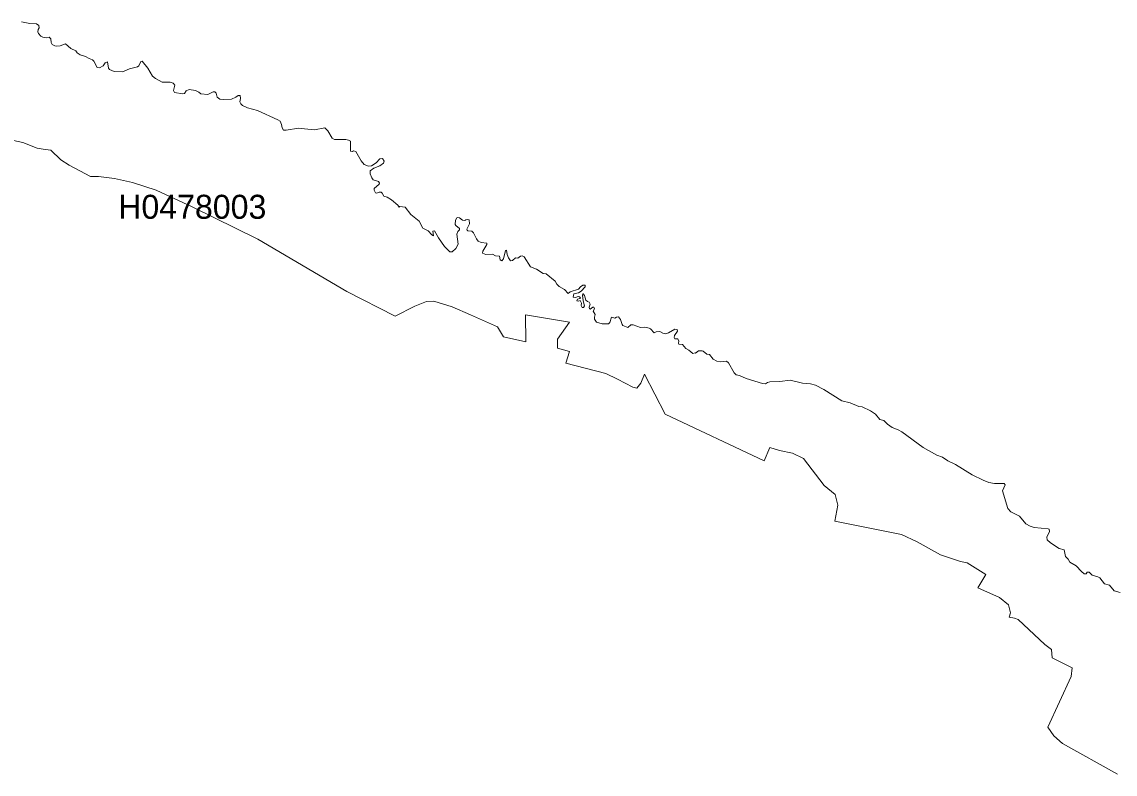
# Model space of a CAD drawing. Extents: x 369010 to 739155, y 6377141 to 6616555.
# Drawn here: x 454336 to 458890, y 6501436 to 6504570 of the extents above; entities that cross this region are included whole.
import ezdxf
from ezdxf.enums import TextEntityAlignment as Align

# ---------------------------------------------------------------- set-up
doc = ezdxf.new("R2010")
doc.units = 0
doc.header["$LTSCALE"] = 40
doc.layers.add('1', color=7, linetype='Continuous', lineweight=13)
doc.layers.add('2', color=7, linetype='Continuous')

msp = doc.modelspace()

# ---------------------------------------------------------------- linework, layer by layer
at = {"layer": '1'}
for points in [[(454578.09, 6504432.26), (454566.34, 6504440.87), (454560.55, 6504449.48), (454539.69, 6504458.74), (454517.02, 6504477.94), (454495.83, 6504470.33), (454481.77, 6504469.01), (454473.49, 6504470.66), (454462.57, 6504476.45), (454458.1, 6504484.73), (454456.28, 6504498.8), (454450.16, 6504506.24), (454437.08, 6504503.6), (454422.85, 6504506.58), (454415.23, 6504511.04), (454404.97, 6504521.64), (454401.83, 6504528.26), (454403.15, 6504538.85), (454407.29, 6504544.97), (454405.97, 6504555.4), (454397.36, 6504561.52), (454369.22, 6504563.51), (454333.97, 6504570.13)], [(455875.48, 6503828.51), (455857.27, 6503839.43), (455843.04, 6503844.39), (455836.09, 6503856.97), (455832.61, 6503859.95), (455824.34, 6503860.94), (455813.41, 6503856.97), (455809.27, 6503858.3), (455803.15, 6503869.22), (455803.48, 6503876.5), (455824, 6503894.54), (455825, 6503898.02), (455822.02, 6503905.13), (455799.68, 6503911.75), (455793.88, 6503920.03), (455787.43, 6503937.08), (455787.1, 6503948.99), (455802.49, 6503961.07), (455827.48, 6503970.67), (455841.88, 6503980.93), (455844.53, 6503989.87), (455838.4, 6504000.79), (455827.48, 6503999.47), (455811.43, 6503982.26), (455791.9, 6503970.01), (455780.48, 6503969.35), (455761.28, 6503976.13), (455749.03, 6503991.2), (455727.02, 6504029.59), (455717.09, 6504032.74), (455712.62, 6504030.25), (455704.18, 6504032.08), (455704.51, 6504072.46), (455696.57, 6504077.59), (455685.31, 6504080.07), (455637.98, 6504079.57), (455629.04, 6504085.86), (455609.84, 6504115.99), (455598.42, 6504128.89), (455554.73, 6504120.45), (455513.19, 6504124.26), (455488.2, 6504126.91), (455436.89, 6504119.13), (455425.47, 6504119.46), (455419.68, 6504128.23), (455417.2, 6504142.3), (455411.4, 6504156.7), (455402.47, 6504162.66), (455317.89, 6504200.23), (455275.69, 6504212.31), (455255.5, 6504221.25), (455247.55, 6504229.02), (455243.25, 6504236.97), (455247.22, 6504251.04), (455245.9, 6504262.95), (455236.63, 6504262.95), (455227.36, 6504256.17), (455208.49, 6504248.55), (455175.73, 6504246.24), (455160.33, 6504247.56), (455149.91, 6504255.84), (455145.77, 6504273.55), (455139.31, 6504278.68), (455132.86, 6504278.01), (455110.19, 6504267.42), (455080.73, 6504269.9), (455073.28, 6504277.02), (455059.21, 6504283.97), (455032.4, 6504288.61), (455020.15, 6504282.81), (455012.87, 6504272.22), (455006.08, 6504270.57), (454971.49, 6504276.36), (454967.02, 6504284.3), (454972.82, 6504306.48), (454965.53, 6504315.09), (454954.28, 6504318.23), (454920.35, 6504319.56), (454892.22, 6504334.62), (454879.64, 6504343.88), (454860.44, 6504376.82), (454836.77, 6504405.95), (454831.31, 6504405.62), (454823.37, 6504386.75), (454818.24, 6504382.94), (454783.98, 6504374.34), (454755.18, 6504361.26), (454720.59, 6504363.08), (454701.06, 6504371.03), (454696.59, 6504377.81), (454692.78, 6504404.13), (454682.85, 6504399), (454675.24, 6504386.75), (454659.85, 6504378.14), (454650.25, 6504379.47), (454636.35, 6504406.28), (454629.73, 6504412.07), (454615.66, 6504417.2), (454601.59, 6504425.81), (454578.09, 6504432.26)], [(454281.18, 6504080.4), (454340.26, 6504067.66), (454399.35, 6504044.49), (454424.67, 6504040.18), (454456.44, 6504036.05), (454498.65, 6503996), (454532.41, 6503972.66), (454621.12, 6503926.15), (454654.88, 6503926.15), (454722.41, 6503917.71), (454796.39, 6503900.83), (454895.53, 6503869.22), (455045.8, 6503799.71), (455318.22, 6503664.49), (455689.78, 6503447.02), (455890.37, 6503343.58), (455972.63, 6503385.78), (456021.78, 6503404.98), (456052.23, 6503406.97), (456128.7, 6503382.97), (456205.33, 6503349.04), (456317.21, 6503299.39), (456341.54, 6503257.52), (456435.21, 6503237.49), (456433.89, 6503349.7), (456617.43, 6503318.75), (456566.62, 6503247.92), (456566.62, 6503210.35), (456617.43, 6503197.11), (456602.04, 6503148.45), (456768.7, 6503105.09), (456817.19, 6503081.75), (456880.58, 6503047.99), (456897.46, 6503043.85), (456914.34, 6503064.87), (456929.24, 6503102.6), (457015.3, 6502936.11), (457428.4, 6502741.14), (457451.07, 6502796.26), (457492.45, 6502784.67), (457545.74, 6502773.58), (457592.08, 6502751.24), (457677.98, 6502638.37)], [(458634.59, 6501595.69), (458609.11, 6501632.1), (458707.08, 6501842.46), (458710.72, 6501878.7), (458628.14, 6501920.08), (458624.83, 6501955.66), (458597.35, 6501976.85), (458485.47, 6502080.29), (458470.74, 6502086.58), (458448.07, 6502089.72), (458454.52, 6502107.76), (458445.09, 6502141.19), (458408.85, 6502171.64), (458317.49, 6502212.19), (458350.75, 6502267.97), (458273.79, 6502315.96), (458245.82, 6502321.92), (458162.24, 6502350.06), (458065.42, 6502403.52), (458000.55, 6502434.3), (457721.67, 6502489.91), (457734.91, 6502556.77), (457723.99, 6502600.63), (457677.98, 6502638.37), (457592.08, 6502751.24), (457545.74, 6502773.58), (457492.45, 6502784.67), (457451.07, 6502796.26), (457428.4, 6502741.14), (457015.3, 6502936.11), (456929.24, 6503102.6), (456914.34, 6503064.87), (456897.46, 6503043.85), (456880.58, 6503047.99), (456817.19, 6503081.75), (456768.7, 6503105.09), (456602.04, 6503148.45), (456617.43, 6503197.11), (456566.62, 6503210.35), (456566.62, 6503247.92), (456617.43, 6503318.75), (456433.89, 6503349.7), (456435.21, 6503237.49), (456341.54, 6503257.52), (456317.21, 6503299.39), (456205.33, 6503349.04), (456128.7, 6503382.97), (456052.23, 6503406.97), (456021.78, 6503404.98), (455972.63, 6503385.78), (455890.37, 6503343.58), (455689.78, 6503447.02), (455318.22, 6503664.49), (455045.8, 6503799.71), (454895.53, 6503869.22), (454796.39, 6503900.83), (454722.41, 6503917.71), (454654.88, 6503926.15), (454621.12, 6503926.15), (454532.41, 6503972.66), (454498.65, 6503996), (454456.44, 6504036.05), (454424.67, 6504040.18), (454399.35, 6504044.49), (454340.26, 6504067.66), (454281.18, 6504080.4)], [(456670.89, 6503431.46), (456674.03, 6503408.29), (456679.83, 6503386.61), (456675.19, 6503380.15), (456669.9, 6503379.99), (456665.43, 6503388.1), (456667.08, 6503398.03), (456661.95, 6503409.28), (456654.83, 6503407.13), (456647.88, 6503407.96), (456650.37, 6503415.08), (456659.63, 6503417.23), (456662.94, 6503420.04), (456658.64, 6503424.51), (456653.84, 6503425.34), (456641.43, 6503421.86), (456631.83, 6503423.68), (456634.97, 6503436.92), (456654.17, 6503441.39), (456665.43, 6503448.01), (456682.97, 6503466.55), (456682.47, 6503473.66), (456672.21, 6503473.33), (456662.94, 6503466.88), (456655.17, 6503456.62), (456619.91, 6503446.03), (456611.97, 6503439.07), (456595.58, 6503455.79), (456574.4, 6503467.21), (456564.47, 6503477.8), (456557.85, 6503489.72), (456519.95, 6503520.17), (456506.87, 6503521.33), (456480.06, 6503539.37), (456454.08, 6503549.63), (456427.76, 6503591.17), (456420.15, 6503595.64), (456412.7, 6503594.48), (456402.44, 6503585.38), (456391.52, 6503587.03), (456380.1, 6503576.44), (456371.16, 6503574.95), (456362.55, 6503587.7), (456357.26, 6503601.27), (456354.94, 6503618.32), (456351.13, 6503617.32), (456342.03, 6503583.39), (456335.58, 6503573.96), (456327.8, 6503578.26), (456326.14, 6503594.32), (456308.27, 6503595.48), (456295.69, 6503602.26), (456269.21, 6503600.94), (456255.14, 6503607.06), (456255.8, 6503615.34), (456273.35, 6503642.31), (456273.02, 6503647.77), (456249.68, 6503650.59), (456237.27, 6503656.71), (456229.49, 6503666.64), (456216.75, 6503690.97), (456209.63, 6503698.25), (456193.91, 6503699.25), (456190.43, 6503702.72), (456190.1, 6503707.19), (456201.02, 6503729.37), (456198.54, 6503744.76), (456193.08, 6503747.24), (456184.64, 6503745.92), (456181.16, 6503742.44), (456171.89, 6503744.1), (456158.82, 6503754.03), (456150.71, 6503755.52), (456147.23, 6503753.7), (456142.1, 6503744.1), (456140.78, 6503726.06), (456143.43, 6503721.26), (456159.15, 6503709.18), (456158.49, 6503703.05), (456151.7, 6503696.6), (456148.23, 6503685.18), (456153.03, 6503644.13), (456144.09, 6503626.26), (456128.7, 6503612.19), (456118.44, 6503612.19), (456096.42, 6503634.87), (456072.09, 6503670.12), (456055.05, 6503699.58), (456047.93, 6503698.42), (456049.92, 6503678.72), (456042.97, 6503682.53), (456029.06, 6503700.24), (456005.73, 6503711.33), (455990.34, 6503739.96), (455956.41, 6503767.77), (455932.41, 6503798.22), (455910.4, 6503801.36), (455907.42, 6503797.56), (455901.46, 6503806.16), (455875.48, 6503828.51)], [(458294.65, 6502683.22), (458225.47, 6502726.41), (458192.86, 6502740.81), (458170.35, 6502756.54), (458147.35, 6502765.14), (458090.08, 6502796.26), (458001.37, 6502861.96), (457985.98, 6502870.9), (457961.65, 6502880.5), (457942.12, 6502894.07), (457926.9, 6502909.13), (457909.19, 6502913.27), (457891.15, 6502935.61), (457871.29, 6502950.34), (457836.04, 6502965.73), (457821.97, 6502968.22), (457786.72, 6502982.95), (457751.46, 6502990.72), (457677.15, 6503038.72), (457641.9, 6503056.93), (457620.88, 6503061.73), (457587.45, 6503064.7), (457535.65, 6503076.79), (457493.28, 6503071.99), (457451.07, 6503070.5), (457441.47, 6503068.18), (457433.86, 6503062.39), (457420.95, 6503063.38), (457352.76, 6503083.74), (457324.63, 6503096.98), (457311.72, 6503099.63), (457302.78, 6503108.23), (457279.45, 6503149.28), (457271.34, 6503156.23), (457245.52, 6503154.41), (457230.46, 6503156.56), (457216.06, 6503165.5), (457200.67, 6503183.87), (457189.08, 6503185.36), (457174.35, 6503197.94), (457169.55, 6503199.76), (457153.83, 6503200.09), (457142.24, 6503190.49), (457140.42, 6503191.81), (457130.82, 6503188.67), (457114.11, 6503203.07), (457102.03, 6503210.02), (457088.12, 6503226.07), (457072.24, 6503226.73), (457070.58, 6503231.2), (457072.9, 6503240.47), (457068.59, 6503249.08), (457056.51, 6503249.08), (457053.04, 6503254.87), (457054.53, 6503262.98), (457066.44, 6503281.51), (457065.12, 6503289.13), (457055.85, 6503290.45), (457028.87, 6503274.4), (457017.45, 6503270.26), (457005.87, 6503273.24), (456993.79, 6503280.52), (456977.73, 6503279.2), (456970.28, 6503275.06), (456954.56, 6503291.11), (456948.93, 6503293.93), (456930.23, 6503297.57), (456912.36, 6503296.58), (456882.9, 6503308.16), (456872.97, 6503307.5), (456860.39, 6503297.07), (456839.7, 6503304.52), (456836.06, 6503309.65), (456829.11, 6503330.17), (456821, 6503341.43), (456813.39, 6503340.1), (456806.1, 6503335.3), (456791.54, 6503339.44), (456784.92, 6503318.09), (456779.79, 6503311.97), (456752.81, 6503311.64), (456729.15, 6503318.59), (456721.2, 6503331.5), (456720.87, 6503340.43), (456724.01, 6503350.7), (456716.07, 6503365.09), (456721.2, 6503374.36), (456717.89, 6503381.48), (456713.75, 6503381.81), (456702.83, 6503373.7), (456701.01, 6503374.36), (456698.36, 6503382.14), (456702.5, 6503393.56), (456698.36, 6503402.83), (456691.41, 6503405.48), (456685.62, 6503410.61), (456679.49, 6503429.48), (456674.69, 6503437.09), (456672.21, 6503436.59), (456670.89, 6503431.46)], [(458910.32, 6502192.17), (458886.32, 6502200.28), (458865.8, 6502223.28), (458846.27, 6502228.41), (458826.41, 6502253.73), (458817.97, 6502258.2), (458793.97, 6502264.99), (458781.89, 6502277.07), (458774.11, 6502278.06), (458769.31, 6502270.95), (458761.37, 6502270.95), (458749.45, 6502280.05), (458727.11, 6502304.05), (458701.46, 6502319.11), (458694.34, 6502332.18), (458683.58, 6502343.44), (458678.12, 6502370.58), (458657.27, 6502375.71), (458621.02, 6502400.37), (458606.95, 6502412.29), (458604.97, 6502423.21), (458615.89, 6502446.88), (458614.9, 6502456.15), (458611.09, 6502458.3), (458552.83, 6502463.43), (458536.12, 6502468.56), (458518.57, 6502479.48), (458491.27, 6502510.93), (458455.35, 6502529.13), (458443.6, 6502542.87), (458421.26, 6502616.85), (458432.02, 6502641.84), (458428.21, 6502646.64), (458387, 6502647.3), (458363.83, 6502651.44), (458340.82, 6502660.21), (458294.65, 6502683.22)], [(457677.98, 6502638.37), (457723.99, 6502600.63), (457734.91, 6502556.77), (457721.67, 6502489.91), (458000.55, 6502434.3), (458065.42, 6502403.52), (458162.24, 6502350.06), (458245.82, 6502321.92), (458273.79, 6502315.96), (458350.75, 6502267.97), (458317.49, 6502212.19), (458408.85, 6502171.64), (458445.09, 6502141.19), (458454.52, 6502107.76), (458448.07, 6502089.72), (458470.74, 6502086.58), (458485.47, 6502080.29), (458597.35, 6501976.85), (458624.83, 6501955.66), (458628.14, 6501920.08), (458710.72, 6501878.7), (458707.08, 6501842.46), (458609.11, 6501632.1), (458634.59, 6501595.69), (458670.84, 6501563.09), (458899.23, 6501436.14)], [(458899.23, 6501436.14), (458670.84, 6501563.09), (458634.59, 6501595.69)]]:
    msp.add_lwpolyline(points, dxfattribs=at)

# ---------------------------------------------------------------- texts
at = {"layer": '2'}
msp.add_text('H0478003', height=100, dxfattribs=at).set_placement((455045.8, 6503749.7), align=Align.CENTER)

doc.saveas('drawing.dxf')
